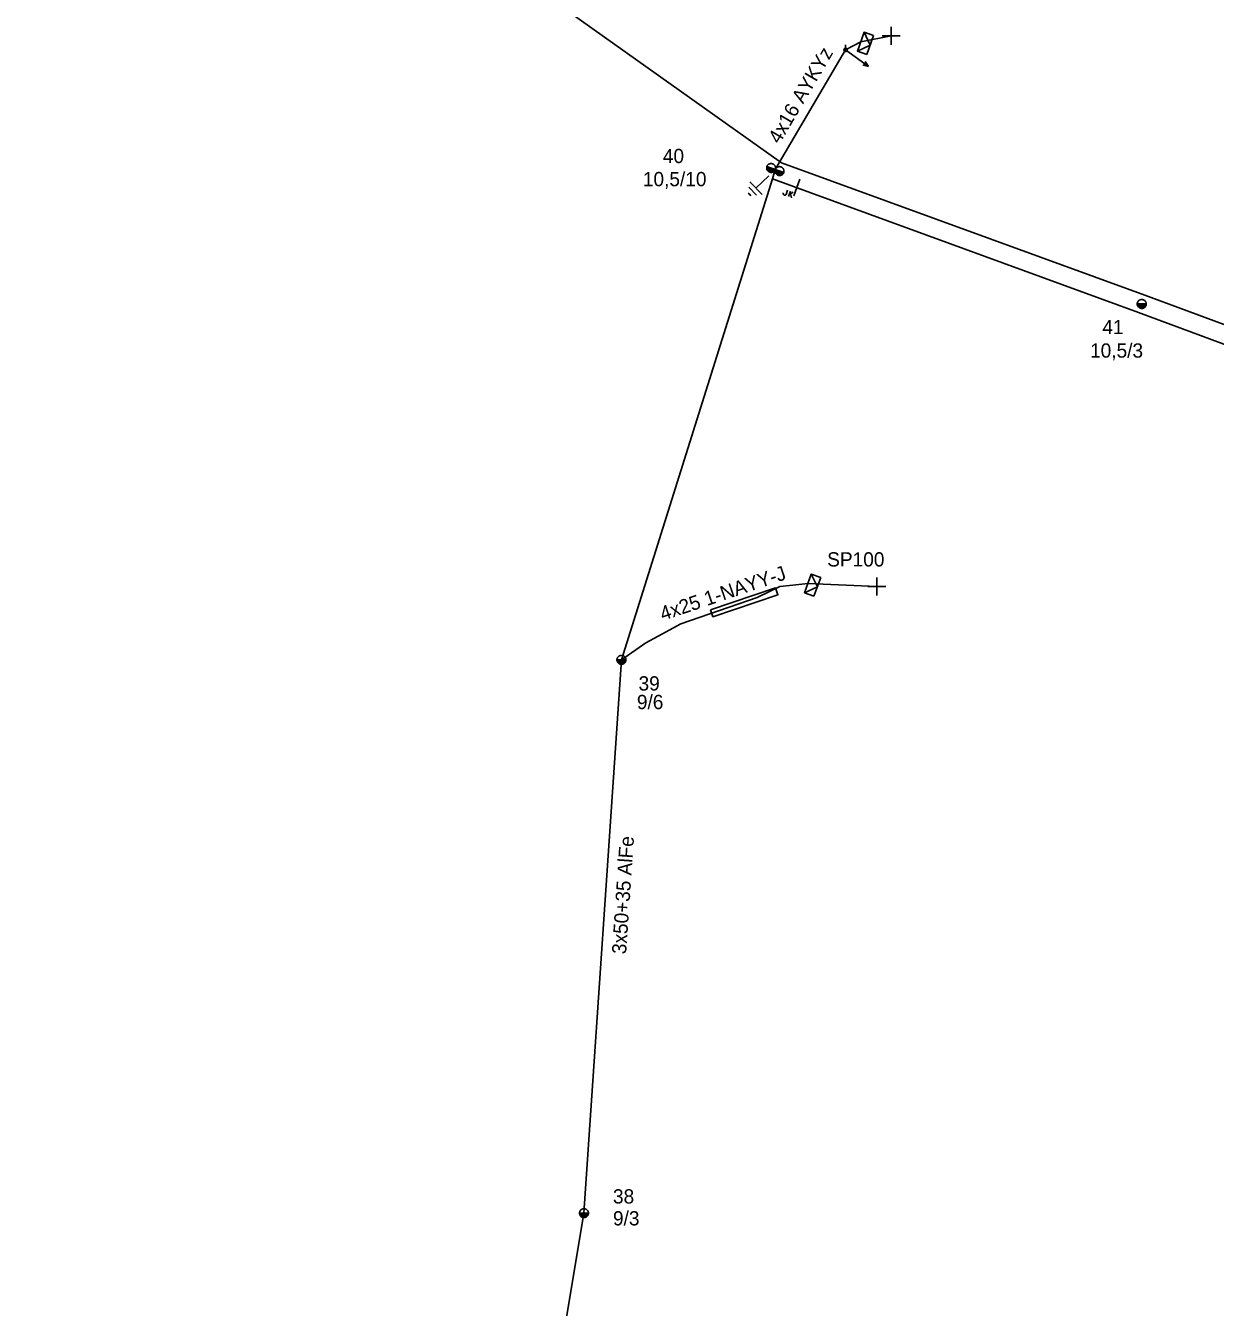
# Model space of a CAD drawing. Extents: x -788458 to -786145, y -1154772 to -1152372.
# Drawn here: x -787370.8 to -787287.4, y -1152817.4 to -1152727.5 of the extents above; entities that cross this region are included whole.
import ezdxf

# ---------------------------------------------------------------- set-up
doc = ezdxf.new("R2010")
doc.units = 0
for name, color, linetype in [('Vrstva 1', 7, 'Continuous'), ('Vrstva 12', 7, 'Continuous'), ('Vrstva 13', 7, 'Continuous'), ('Vrstva 14', 7, 'Continuous'), ('Vrstva 15', 7, 'Continuous'), ('Vrstva 18', 7, 'Continuous'), ('Vrstva 2', 7, 'Continuous'), ('Vrstva 20', 7, 'Continuous'), ('Vrstva 31', 7, 'Continuous'), ('Vrstva 33', 7, 'Continuous'), ('Vrstva 34', 7, 'Continuous'), ('Vrstva 52', 7, 'Continuous'), ('Vrstva 53', 7, 'Continuous'), ('Vrstva 54', 7, 'Continuous'), ('Vrstva 59', 7, 'Continuous'), ('Vrstva 9', 7, 'Continuous')]:
    doc.layers.add(name, color=color, linetype=linetype)

# ---------------------------------------------------------------- blocks, each defined once
blk = doc.blocks.new('NN440')
at = {"layer": 'Vrstva 2'}
for points in [[(0.63, 0), (0.63, 0.06), (0.62, 0.13), (0.6, 0.19), (0.58, 0.25), (0.55, 0.31), (0.51, 0.37), (0.47, 0.42), (0.42, 0.46), (0.37, 0.51), (0.32, 0.54), (0.26, 0.57), (0.2, 0.59), (0.13, 0.61), (0.07, 0.62), (0, 0.63), (-0.06, 0.62), (-0.13, 0.61), (-0.19, 0.59), (-0.26, 0.57), (-0.31, 0.54), (-0.37, 0.51), (-0.42, 0.46), (-0.47, 0.42), (-0.51, 0.37), (-0.54, 0.31), (-0.57, 0.25), (-0.6, 0.19), (-0.62, 0.13), (-0.63, 0.06), (-0.63, 0), (-0.63, -0.07), (-0.62, -0.14), (-0.6, -0.2), (-0.57, -0.26), (-0.54, -0.32), (-0.51, -0.37), (-0.47, -0.43), (-0.42, -0.47), (-0.37, -0.51), (-0.31, -0.55), (-0.26, -0.58), (-0.19, -0.6), (-0.13, -0.62), (-0.06, -0.63), (0, -0.63), (0.07, -0.63), (0.13, -0.62), (0.2, -0.6), (0.26, -0.58), (0.32, -0.55), (0.37, -0.51), (0.42, -0.47), (0.47, -0.43), (0.51, -0.37), (0.55, -0.32), (0.58, -0.26), (0.6, -0.2), (0.62, -0.14), (0.63, -0.07), (0.63, 0)], [(-0.63, 0), (0.63, 0)], [(-0.6, -0.18), (0.57, -0.18)], [(-0.51, -0.32), (0.5, -0.32)], [(-0.37, -0.47), (0.35, -0.47)]]:
    blk.add_lwpolyline(points, dxfattribs=at)
blk = doc.blocks.new('NN450')
at = {"layer": 'Vrstva 2'}
for points in [[(0, 0), (0, 0.07), (-0.01, 0.13), (-0.03, 0.19), (-0.05, 0.25), (-0.08, 0.31), (-0.12, 0.37), (-0.16, 0.42), (-0.21, 0.46), (-0.26, 0.51), (-0.31, 0.54), (-0.37, 0.57), (-0.43, 0.59), (-0.5, 0.61), (-0.56, 0.62), (-0.63, 0.62), (-0.69, 0.62), (-0.75, 0.61), (-0.82, 0.59), (-0.88, 0.57), (-0.94, 0.54), (-0.99, 0.51), (-1.04, 0.46), (-1.09, 0.42), (-1.13, 0.37), (-1.17, 0.31), (-1.2, 0.25), (-1.22, 0.19), (-1.24, 0.13), (-1.25, 0.07), (-1.25, 0), (-1.25, -0.07), (-1.24, -0.13), (-1.22, -0.19), (-1.2, -0.25), (-1.17, -0.31), (-1.13, -0.37), (-1.09, -0.42), (-1.04, -0.46), (-0.99, -0.51), (-0.94, -0.54), (-0.88, -0.57), (-0.82, -0.59), (-0.75, -0.61), (-0.69, -0.62), (-0.62, -0.63), (-0.56, -0.62), (-0.5, -0.61), (-0.43, -0.59), (-0.37, -0.57), (-0.31, -0.54), (-0.26, -0.51), (-0.21, -0.46), (-0.16, -0.42), (-0.12, -0.37), (-0.08, -0.31), (-0.05, -0.25), (-0.03, -0.19), (-0.01, -0.13), (0, -0.07), (0, 0)], [(1.25, 0), (1.25, 0.07), (1.24, 0.13), (1.22, 0.19), (1.2, 0.25), (1.17, 0.31), (1.13, 0.37), (1.09, 0.42), (1.04, 0.46), (0.99, 0.51), (0.94, 0.54), (0.88, 0.57), (0.82, 0.59), (0.75, 0.61), (0.69, 0.62), (0.62, 0.62), (0.56, 0.62), (0.5, 0.61), (0.43, 0.59), (0.37, 0.57), (0.31, 0.54), (0.26, 0.51), (0.21, 0.46), (0.16, 0.42), (0.12, 0.37), (0.08, 0.31), (0.05, 0.25), (0.03, 0.19), (0.01, 0.13), (0, 0.07), (0, 0), (0, -0.07), (0.01, -0.13), (0.03, -0.19), (0.05, -0.25), (0.08, -0.31), (0.12, -0.37), (0.16, -0.42), (0.21, -0.46), (0.26, -0.51), (0.31, -0.54), (0.37, -0.57), (0.43, -0.59), (0.5, -0.61), (0.56, -0.62), (0.63, -0.63), (0.69, -0.62), (0.75, -0.61), (0.82, -0.59), (0.88, -0.57), (0.94, -0.54), (0.99, -0.51), (1.04, -0.46), (1.09, -0.42), (1.13, -0.37), (1.17, -0.31), (1.2, -0.25), (1.22, -0.19), (1.24, -0.13), (1.25, -0.07), (1.25, 0)], [(-1.25, 0), (1.25, 0)], [(-1.23, -0.16), (-0.02, -0.16)], [(-1.16, -0.32), (-0.09, -0.32)], [(-1.03, -0.47), (-0.22, -0.47)], [(0.02, -0.16), (1.23, -0.16)], [(0.09, -0.32), (1.16, -0.32)], [(0.22, -0.47), (1.03, -0.47)]]:
    blk.add_lwpolyline(points, dxfattribs=at)
blk = doc.blocks.new('NN560')
at = {"layer": 'Vrstva 2'}
for points in [[(1.999, -0.001), (1.59, 0.141)], [(0, -0.001), (1.999, -0.001)], [(1.999, -0.001), (1.59, -0.134)]]:
    blk.add_lwpolyline(points, dxfattribs=at)
blk = doc.blocks.new('NN840')
at = {"layer": 'Vrstva 15'}
for points in [[(0.003, 0.619), (0.003, -0.631)], [(-0.745, -0.71), (-0.745, -0.66)], [(-0.73, -0.764), (-0.745, -0.71)], [(-0.657, -0.798), (-0.73, -0.764)], [(-0.627, -0.798), (-0.657, -0.798)], [(-0.558, -0.764), (-0.627, -0.798)], [(-0.538, -0.71), (-0.558, -0.764)], [(-0.538, -0.385), (-0.538, -0.71)], [(-0.332, -0.385), (-0.332, -0.798)], [(-0.332, -0.641), (-0.125, -0.385)], [(-0.263, -0.557), (-0.091, -0.798)]]:
    blk.add_lwpolyline(points, dxfattribs=at)
blk = doc.blocks.new('NN800')
at = {"layer": 'Vrstva 1'}
for points in [[(-0.442, 0.442), (0.442, -0.442)], [(-0.442, -0.442), (0.442, 0.442)]]:
    blk.add_lwpolyline(points, dxfattribs=at)
blk = doc.blocks.new('NN630')
at = {"layer": 'Vrstva 9'}
for points in [[(-0.003, -0.7), (-0.703, 0)], [(-0.703, -0.7), (-0.703, 0), (0.697, 0), (0.697, -0.7)], [(-0.703, -0.7), (0.697, -0.7)], [(-0.003, -0.7), (0.697, 0)]]:
    blk.add_lwpolyline(points, dxfattribs=at)
blk = doc.blocks.new('NN810')
at = {"layer": 'Vrstva 14'}
for points in [[(0.004, -0.64), (0.004, -1.89)], [(0.629, -1.89), (-0.621, -1.89)], [(0.388, -2.2), (-0.399, -2.2)], [(0.004, -2.515), (-0.124, -2.515)], [(0.137, -2.515), (0.004, -2.515)]]:
    blk.add_lwpolyline(points, dxfattribs=at)
blk = doc.blocks.new('NN500')
at = {"layer": 'Vrstva 2'}
for points in [[(0, -0.24), (0.02, -0.23), (0.05, -0.23), (0.07, -0.22), (0.09, -0.22), (0.12, -0.2), (0.14, -0.19), (0.16, -0.18), (0.17, -0.16), (0.19, -0.14), (0.2, -0.12), (0.21, -0.1), (0.22, -0.07), (0.23, -0.05), (0.23, -0.02), (0.23, 0), (0.23, 0.02), (0.23, 0.05), (0.22, 0.07), (0.21, 0.1), (0.2, 0.12), (0.19, 0.14), (0.17, 0.16), (0.16, 0.17), (0.14, 0.19), (0.12, 0.2), (0.09, 0.21), (0.07, 0.22), (0.05, 0.23), (0.02, 0.23), (0, 0.23), (-0.03, 0.23), (-0.05, 0.23), (-0.07, 0.22), (-0.1, 0.21), (-0.12, 0.2), (-0.14, 0.19), (-0.16, 0.17), (-0.18, 0.16), (-0.19, 0.14), (-0.2, 0.12), (-0.22, 0.1), (-0.22, 0.07), (-0.23, 0.05), (-0.23, 0.02), (-0.24, 0), (-0.23, -0.02), (-0.23, -0.05), (-0.22, -0.07), (-0.22, -0.1), (-0.2, -0.12), (-0.19, -0.14), (-0.18, -0.16), (-0.16, -0.18), (-0.14, -0.19), (-0.12, -0.2), (-0.1, -0.22), (-0.07, -0.22), (-0.05, -0.23), (-0.03, -0.23), (0, -0.24)], [(0, -0.24), (0.02, -0.23), (0.05, -0.23), (0.07, -0.22), (0.09, -0.22), (0.12, -0.2), (0.14, -0.19), (0.16, -0.18), (0.17, -0.16), (0.19, -0.14), (0.2, -0.12), (0.21, -0.1), (0.22, -0.07), (0.23, -0.05), (0.23, -0.02), (0.23, 0), (0.23, 0.02), (0.23, 0.05), (0.22, 0.07), (0.21, 0.1), (0.2, 0.12), (0.19, 0.14), (0.17, 0.16), (0.16, 0.17), (0.14, 0.19), (0.12, 0.2), (0.09, 0.21), (0.07, 0.22), (0.05, 0.23), (0.02, 0.23), (0, 0.23), (-0.03, 0.23), (-0.05, 0.23), (-0.07, 0.22), (-0.1, 0.21), (-0.12, 0.2), (-0.14, 0.19), (-0.16, 0.17), (-0.18, 0.16), (-0.19, 0.14), (-0.2, 0.12), (-0.22, 0.1), (-0.22, 0.07), (-0.23, 0.05), (-0.23, 0.02), (-0.24, 0), (-0.23, -0.02), (-0.23, -0.05), (-0.22, -0.07), (-0.22, -0.1), (-0.2, -0.12), (-0.19, -0.14), (-0.18, -0.16), (-0.16, -0.18), (-0.14, -0.19), (-0.12, -0.2), (-0.1, -0.22), (-0.07, -0.22), (-0.05, -0.23), (-0.03, -0.23), (0, -0.24)], [(0, -0.21), (0.02, -0.2), (0.04, -0.2), (0.06, -0.2), (0.08, -0.19), (0.1, -0.18), (0.12, -0.17), (0.14, -0.15), (0.15, -0.14), (0.16, -0.12), (0.18, -0.1), (0.19, -0.08), (0.19, -0.06), (0.2, -0.04), (0.2, -0.02), (0.2, 0), (0.2, 0.02), (0.2, 0.04), (0.19, 0.06), (0.19, 0.08), (0.18, 0.1), (0.16, 0.12), (0.15, 0.14), (0.14, 0.15), (0.12, 0.17), (0.1, 0.18), (0.08, 0.19), (0.06, 0.19), (0.04, 0.2), (0.02, 0.2), (0, 0.2), (-0.02, 0.2), (-0.04, 0.2), (-0.06, 0.19), (-0.08, 0.19), (-0.1, 0.18), (-0.12, 0.17), (-0.14, 0.15), (-0.15, 0.14), (-0.17, 0.12), (-0.18, 0.1), (-0.19, 0.08), (-0.2, 0.06), (-0.2, 0.04), (-0.21, 0.02), (-0.21, 0), (-0.21, -0.02), (-0.2, -0.04), (-0.2, -0.06), (-0.19, -0.08), (-0.18, -0.1), (-0.17, -0.12), (-0.15, -0.14), (-0.14, -0.15), (-0.12, -0.17), (-0.1, -0.18), (-0.08, -0.19), (-0.06, -0.2), (-0.04, -0.2), (-0.02, -0.2), (0, -0.21)], [(0, -0.18), (0.02, -0.18), (0.04, -0.17), (0.05, -0.17), (0.07, -0.16), (0.09, -0.15), (0.1, -0.14), (0.12, -0.13), (0.13, -0.12), (0.14, -0.1), (0.15, -0.09), (0.16, -0.07), (0.17, -0.05), (0.17, -0.04), (0.17, -0.02), (0.17, 0), (0.17, 0.02), (0.17, 0.04), (0.17, 0.05), (0.16, 0.07), (0.15, 0.09), (0.14, 0.1), (0.13, 0.12), (0.12, 0.13), (0.1, 0.14), (0.09, 0.15), (0.07, 0.16), (0.05, 0.17), (0.04, 0.17), (0.02, 0.17), (0, 0.18), (-0.02, 0.17), (-0.04, 0.17), (-0.06, 0.17), (-0.07, 0.16), (-0.09, 0.15), (-0.1, 0.14), (-0.12, 0.13), (-0.13, 0.12), (-0.14, 0.1), (-0.15, 0.09), (-0.16, 0.07), (-0.17, 0.05), (-0.17, 0.04), (-0.18, 0.02), (-0.18, 0), (-0.18, -0.02), (-0.17, -0.04), (-0.17, -0.05), (-0.16, -0.07), (-0.15, -0.09), (-0.14, -0.1), (-0.13, -0.12), (-0.12, -0.13), (-0.1, -0.14), (-0.09, -0.15), (-0.07, -0.16), (-0.06, -0.17), (-0.04, -0.17), (-0.02, -0.18), (0, -0.18)], [(0, -0.15), (0.01, -0.15), (0.03, -0.14), (0.04, -0.14), (0.06, -0.13), (0.07, -0.13), (0.08, -0.12), (0.1, -0.11), (0.11, -0.1), (0.12, -0.09), (0.13, -0.07), (0.13, -0.06), (0.14, -0.05), (0.14, -0.03), (0.14, -0.02), (0.14, 0), (0.14, 0.01), (0.14, 0.03), (0.14, 0.04), (0.13, 0.06), (0.13, 0.07), (0.12, 0.09), (0.11, 0.1), (0.1, 0.11), (0.08, 0.12), (0.07, 0.13), (0.06, 0.13), (0.04, 0.14), (0.03, 0.14), (0.01, 0.14), (0, 0.15), (-0.02, 0.14), (-0.03, 0.14), (-0.05, 0.14), (-0.06, 0.13), (-0.07, 0.13), (-0.09, 0.12), (-0.1, 0.11), (-0.11, 0.1), (-0.12, 0.09), (-0.13, 0.07), (-0.13, 0.06), (-0.14, 0.04), (-0.14, 0.03), (-0.15, 0.01), (-0.15, 0), (-0.15, -0.02), (-0.14, -0.03), (-0.14, -0.05), (-0.13, -0.06), (-0.13, -0.07), (-0.12, -0.09), (-0.11, -0.1), (-0.1, -0.11), (-0.09, -0.12), (-0.07, -0.13), (-0.06, -0.13), (-0.05, -0.14), (-0.03, -0.14), (-0.02, -0.15), (0, -0.15)], [(0, -0.12), (0.01, -0.12), (0.02, -0.11), (0.03, -0.11), (0.05, -0.11), (0.06, -0.1), (0.07, -0.09), (0.08, -0.09), (0.09, -0.08), (0.09, -0.07), (0.1, -0.06), (0.11, -0.05), (0.11, -0.04), (0.11, -0.02), (0.11, -0.01), (0.12, 0), (0.11, 0.01), (0.11, 0.02), (0.11, 0.04), (0.11, 0.05), (0.1, 0.06), (0.09, 0.07), (0.09, 0.08), (0.08, 0.09), (0.07, 0.09), (0.06, 0.1), (0.05, 0.11), (0.03, 0.11), (0.02, 0.11), (0.01, 0.12), (0, 0.12), (-0.01, 0.12), (-0.03, 0.11), (-0.04, 0.11), (-0.05, 0.11), (-0.06, 0.1), (-0.07, 0.09), (-0.08, 0.09), (-0.09, 0.08), (-0.1, 0.07), (-0.1, 0.06), (-0.11, 0.05), (-0.11, 0.04), (-0.12, 0.02), (-0.12, 0.01), (-0.12, 0), (-0.12, -0.01), (-0.12, -0.02), (-0.11, -0.04), (-0.11, -0.05), (-0.1, -0.06), (-0.1, -0.07), (-0.09, -0.08), (-0.08, -0.09), (-0.07, -0.09), (-0.06, -0.1), (-0.05, -0.11), (-0.04, -0.11), (-0.03, -0.11), (-0.01, -0.12), (0, -0.12)], [(0, -0.09), (0.01, -0.09), (0.02, -0.09), (0.03, -0.08), (0.03, -0.08), (0.04, -0.08), (0.05, -0.07), (0.06, -0.07), (0.06, -0.06), (0.07, -0.05), (0.07, -0.04), (0.08, -0.04), (0.08, -0.03), (0.08, -0.02), (0.09, -0.01), (0.09, 0), (0.09, 0.01), (0.08, 0.02), (0.08, 0.03), (0.08, 0.03), (0.07, 0.04), (0.07, 0.05), (0.06, 0.06), (0.06, 0.06), (0.05, 0.07), (0.04, 0.07), (0.03, 0.08), (0.03, 0.08), (0.02, 0.08), (0.01, 0.09), (0, 0.09), (-0.01, 0.09), (-0.02, 0.08), (-0.03, 0.08), (-0.04, 0.08), (-0.04, 0.07), (-0.05, 0.07), (-0.06, 0.06), (-0.07, 0.06), (-0.07, 0.05), (-0.08, 0.04), (-0.08, 0.03), (-0.08, 0.03), (-0.09, 0.02), (-0.09, 0.01), (-0.09, 0), (-0.09, -0.01), (-0.09, -0.02), (-0.08, -0.03), (-0.08, -0.04), (-0.08, -0.04), (-0.07, -0.05), (-0.07, -0.06), (-0.06, -0.07), (-0.05, -0.07), (-0.04, -0.08), (-0.04, -0.08), (-0.03, -0.08), (-0.02, -0.09), (-0.01, -0.09), (0, -0.09)], [(0, -0.06), (0, -0.06), (0.01, -0.06), (0.02, -0.05), (0.02, -0.05), (0.03, -0.05), (0.03, -0.05), (0.04, -0.04), (0.04, -0.04), (0.05, -0.03), (0.05, -0.03), (0.05, -0.02), (0.05, -0.02), (0.05, -0.01), (0.06, -0.01), (0.06, 0), (0.06, 0.01), (0.05, 0.01), (0.05, 0.02), (0.05, 0.02), (0.05, 0.03), (0.05, 0.03), (0.04, 0.04), (0.04, 0.04), (0.03, 0.05), (0.03, 0.05), (0.02, 0.05), (0.02, 0.05), (0.01, 0.06), (0, 0.06), (0, 0.06), (-0.01, 0.06), (-0.01, 0.06), (-0.02, 0.05), (-0.02, 0.05), (-0.03, 0.05), (-0.03, 0.05), (-0.04, 0.04), (-0.04, 0.04), (-0.05, 0.03), (-0.05, 0.03), (-0.05, 0.02), (-0.06, 0.02), (-0.06, 0.01), (-0.06, 0.01), (-0.06, 0), (-0.06, -0.01), (-0.06, -0.01), (-0.06, -0.02), (-0.05, -0.02), (-0.05, -0.03), (-0.05, -0.03), (-0.04, -0.04), (-0.04, -0.04), (-0.03, -0.05), (-0.03, -0.05), (-0.02, -0.05), (-0.02, -0.05), (-0.01, -0.06), (-0.01, -0.06), (0, -0.06)], [(0, -0.03), (0, -0.03), (0, -0.03), (0.01, -0.03), (0.01, -0.03), (0.01, -0.02), (0.02, -0.02), (0.02, -0.02), (0.02, -0.02), (0.02, -0.02), (0.02, -0.01), (0.02, -0.01), (0.03, -0.01), (0.03, -0.01), (0.03, 0), (0.03, 0), (0.03, 0), (0.03, 0.01), (0.03, 0.01), (0.02, 0.01), (0.02, 0.01), (0.02, 0.02), (0.02, 0.02), (0.02, 0.02), (0.02, 0.02), (0.01, 0.02), (0.01, 0.02), (0.01, 0.03), (0, 0.03), (0, 0.03), (0, 0.03), (0, 0.03), (-0.01, 0.03), (-0.01, 0.03), (-0.01, 0.02), (-0.02, 0.02), (-0.02, 0.02), (-0.02, 0.02), (-0.02, 0.02), (-0.02, 0.02), (-0.03, 0.01), (-0.03, 0.01), (-0.03, 0.01), (-0.03, 0.01), (-0.03, 0), (-0.03, 0), (-0.03, 0), (-0.03, -0.01), (-0.03, -0.01), (-0.03, -0.01), (-0.03, -0.01), (-0.02, -0.02), (-0.02, -0.02), (-0.02, -0.02), (-0.02, -0.02), (-0.02, -0.02), (-0.01, -0.03), (-0.01, -0.03), (-0.01, -0.03), (0, -0.03), (0, -0.03)], [(0.23, 0), (0.7, 0)]]:
    blk.add_lwpolyline(points, dxfattribs=at)

msp = doc.modelspace()

# ---------------------------------------------------------------- linework, layer by layer
at = {"layer": 'Vrstva 1'}
for points in [[(-787327.741, -1152703.401), (-787337.42, -1152723.22), (-787317.82, -1152737.159), (-787292.344, -1152746.434), (-787268.103, -1152755.42), (-787235.599, -1152767.697), (-787219.01, -1152771.91)], [(-787370.84, -1152932.51), (-787352.71, -1152886.68), (-787338.36, -1152850.84), (-787331.68, -1152810.84), (-787329.05, -1152772.02), (-787318.461, -1152738.272)], [(-787268.588, -1152756.647), (-787292.795, -1152747.666), (-787318.461, -1152738.272)]]:
    msp.add_lwpolyline(points, dxfattribs=at)
at = {"layer": 'Vrstva 20'}
msp.add_lwpolyline([(-787322.801, -1152768.523), (-787318.241, -1152766.983), (-787318.081, -1152767.457), (-787322.641, -1152768.997)], close=True, dxfattribs=at)
at = {"layer": 'Vrstva 52'}
for points in [[(-787313.33, -1152729.23), (-787312.265, -1152728.662)], [(-787313.33, -1152729.23), (-787318.26, -1152737.63), (-787318.461, -1152738.272)], [(-787329.05, -1152772.02), (-787327.34, -1152770.84), (-787326.473, -1152770.371), (-787324.88, -1152769.51), (-787319.54, -1152767.66), (-787317.94, -1152766.89), (-787317.03, -1152766.79), (-787315.97, -1152766.66)]]:
    msp.add_lwpolyline(points, dxfattribs=at)
at = {"layer": 'Vrstva 59'}
for points in [[(-787312.265, -1152728.662), (-787310.13, -1152728.25)], [(-787315.97, -1152766.66), (-787311.14, -1152766.88)]]:
    msp.add_lwpolyline(points, dxfattribs=at)

# ---------------------------------------------------------------- block references
at = {"layer": 'Vrstva 13', "xscale": 0.5, "yscale": 0.5}
for name, p, rotation in [('NN500', (-787313.33, -1152729.23), 90), ('NN450', (-787318.26, -1152737.63), -20.149403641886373)]:
    msp.add_blockref(name, p, dxfattribs=dict(at, rotation=rotation))
at = {"layer": 'Vrstva 13', "rotation": -36.03435279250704}
msp.add_blockref('NN560', (-787313.33, -1152729.23), dxfattribs=at)
at = {"layer": 'Vrstva 13', "xscale": 0.5, "yscale": 0.5}
for p in [(-787292.56, -1152747.06), (-787329.05, -1152772.02), (-787331.68, -1152810.84)]:
    msp.add_blockref('NN440', p, dxfattribs=at)
at = {"layer": 'Vrstva 15', "rotation": -46.327077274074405}
msp.add_blockref('NN810', (-787318.26, -1152737.63), dxfattribs=at)
at = {"layer": 'Vrstva 18', "rotation": -19.986751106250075}
msp.add_blockref('NN840', (-787316.758, -1152738.892), dxfattribs=at)
at = {"layer": 'Vrstva 31'}
for p, rotation in [((-787312.265, -1152728.662), 70.64100559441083), ((-787315.97, -1152766.66), 70.34617596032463)]:
    msp.add_blockref('NN630', p, dxfattribs=dict(at, rotation=rotation))
at = {"layer": 'Vrstva 34', "rotation": 45}
for p in [(-787310.13, -1152728.25), (-787311.14, -1152766.88)]:
    msp.add_blockref('NN800', p, dxfattribs=at)

# ---------------------------------------------------------------- texts
at = {"layer": 'Vrstva 12'}
for s, p in [('10,5/10', (-787327.55, -1152738.8)), ('10,5/3', (-787296.184, -1152750.826)), ('9/6', (-787327.969, -1152775.482)), ('9/3', (-787329.646, -1152811.701))]:
    msp.add_text(s, height=1, dxfattribs=at).set_placement(p)
at = {"layer": 'Vrstva 14'}
for s, p in [('40', (-787326.148, -1152737.178)), ('41', (-787295.321, -1152749.177)), ('39', (-787327.852, -1152774.178)), ('38', (-787329.646, -1152810.164))]:
    msp.add_text(s, height=1, dxfattribs=at).set_placement(p)
at = {"layer": 'Vrstva 2'}
msp.add_text('3x50+35 AlFe', height=1, rotation=86.124, dxfattribs=at).set_placement((-787328.728, -1152792.694))
at = {"layer": 'Vrstva 33'}
msp.add_text('SP100', height=1, dxfattribs=at).set_placement((-787314.622, -1152765.477))
at = {"layer": 'Vrstva 53'}
msp.add_text('4x16 AYKYz', height=1, rotation=59.591, dxfattribs=at).set_placement((-787317.966, -1152735.891))
at = {"layer": 'Vrstva 54'}
msp.add_text('4x25 1-NAYY-J', height=1, rotation=18.661, dxfattribs=at).set_placement((-787326.152, -1152769.299))

doc.saveas('drawing.dxf')
